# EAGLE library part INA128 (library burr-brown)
Instrumentation Amplifiers Precision, Low Power
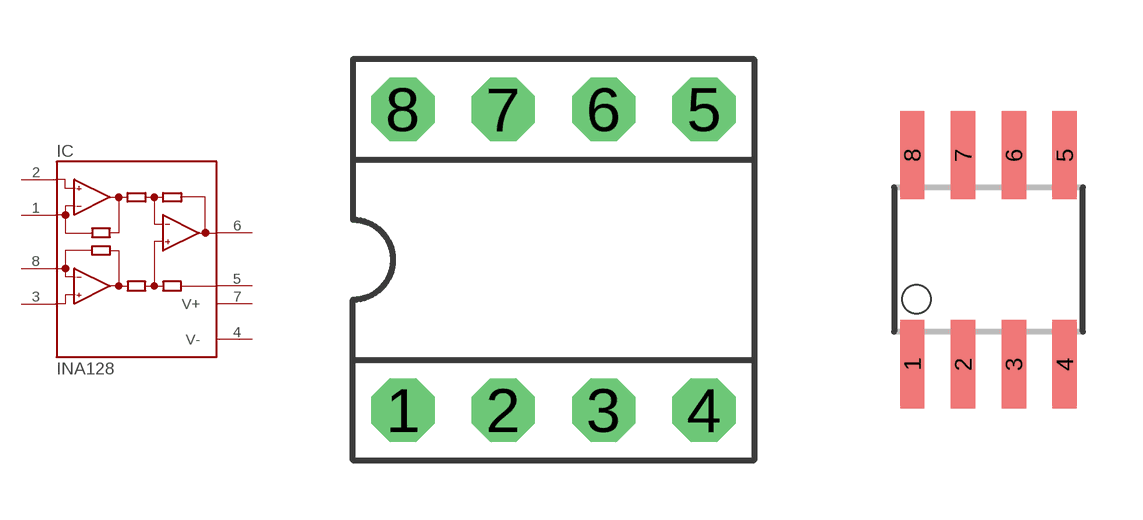
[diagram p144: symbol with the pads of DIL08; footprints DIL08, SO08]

Designator prefix IC

## INA128P (MF: TEXAS INSTRUMENTS; MPN: INA128P; OC_FARNELL: 1212410; OC_NEWARK: 74C9783)  [DIL08]
1  RG  pas
2  -IN  in
3  +IN  in
4  V-  pwr
5  REF  pas
6  OUT  out
7  V+  pwr
8  RG  pas

## INA128U (MF: TEXAS INSTRUMENTS; MPN: INA128U; OC_FARNELL: 1212413; OC_NEWARK: 35C1729)  [SO08]
Pads as for DIL08

## Footprint DIL08 (pad centres in mm)
Dual In Line
drill 0.813 pad 1.6 octagon: 1 -3.81,-3.81; 2 -1.27,-3.81; 3 1.27,-3.81; 4 3.81,-3.81; 5 3.81,3.81; 6 1.27,3.81; 7 -1.27,3.81; 8 -3.81,3.81

## Footprint SO08 (pad centres in mm)
Small Outline Package
smd 0.61 x 2.21: 1 -1.905,-2.616; 2 -0.635,-2.616; 3 0.635,-2.616; 4 1.905,-2.616; 5 1.905,2.616; 6 0.635,2.616; 7 -0.635,2.616; 8 -1.905,2.616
